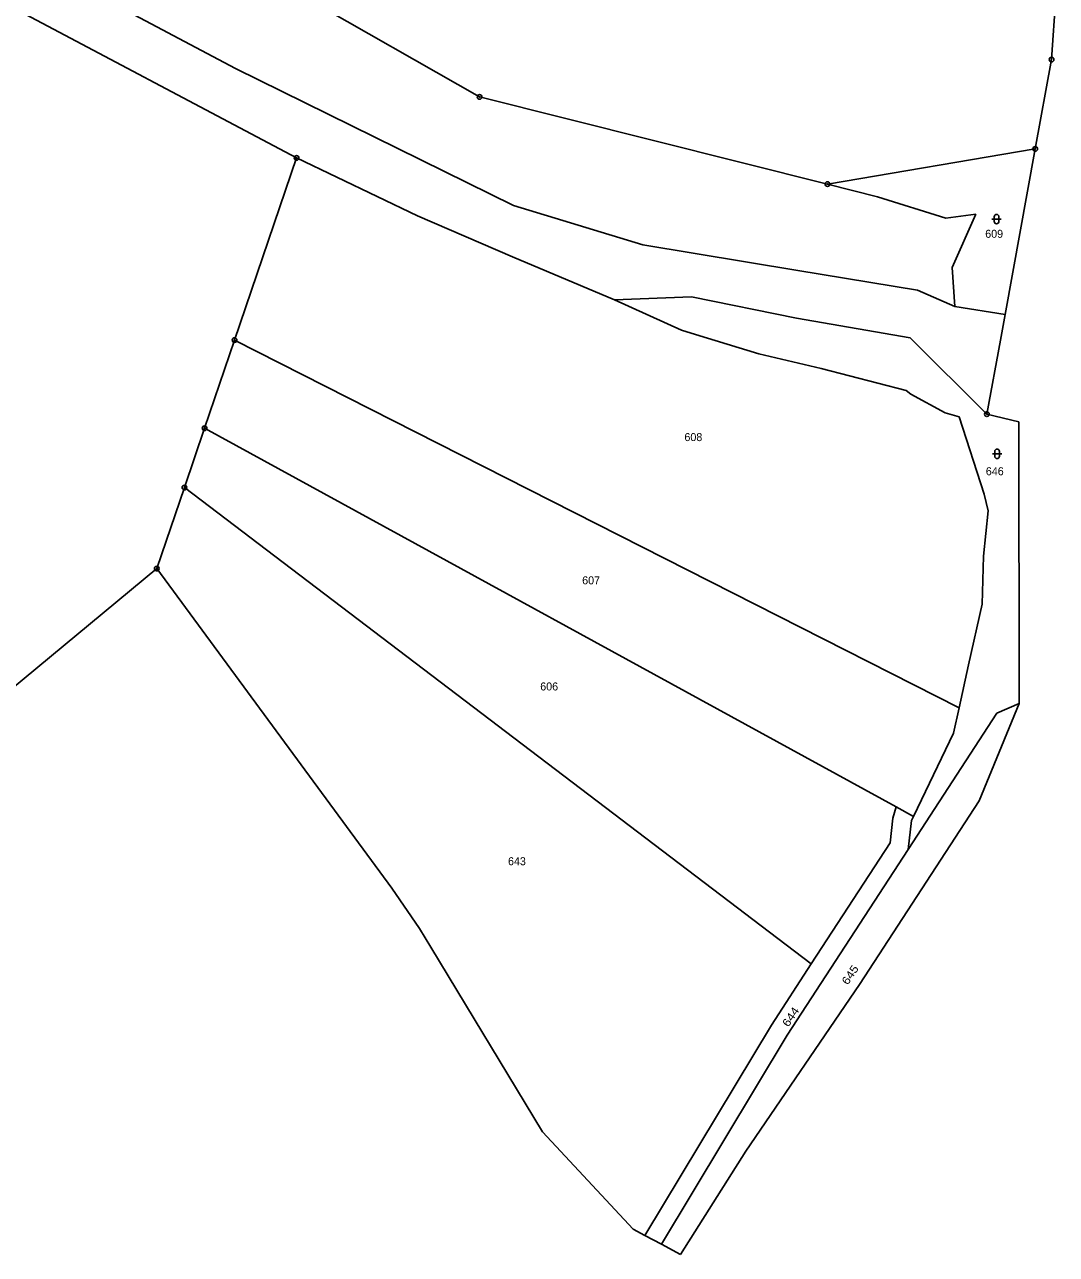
# Model space of a CAD drawing. Extents: x -719614 to -717765, y -1095834 to -1093862.
# Drawn here: x -718549.9 to -718330.6, y -1095834.3 to -1095573 of the extents above; entities that cross this region are included whole.
import ezdxf
from ezdxf.enums import TextEntityAlignment as Align

# ---------------------------------------------------------------- set-up
doc = ezdxf.new("R2010")
doc.units = 0
doc.header["$LTSCALE"] = 0.68
for name, color, linetype, lineweight in [('1', 7, 'Continuous', 25), ('3', 7, 'Continuous', 25), ('8', 7, 'Continuous', 25)]:
    doc.layers.add(name, color=color, linetype=linetype, lineweight=lineweight)
doc.layers.add('2', color=7, linetype='Continuous')

msp = doc.modelspace()

# ---------------------------------------------------------------- linework, layer by layer
at = {"layer": '1'}
for p, q in [((-718453.18, -1095588.42), (-718515.95, -1095552.63)), ((-718492.07, -1095601.38), (-718570.21, -1095559.91)), ((-718546.41, -1095560.42), (-718505.05, -1095582.36)), ((-718331.65, -1095580.47), (-718330.61, -1095565.64)), ((-718335.11, -1095599.47), (-718331.65, -1095580.47)), ((-718505.05, -1095582.36), (-718445.99, -1095611.48)), ((-718379.27, -1095606.93), (-718453.18, -1095588.42)), ((-718335.11, -1095599.47), (-718379.27, -1095606.93)), ((-718341.52, -1095634.63), (-718335.11, -1095599.47)), ((-718492.07, -1095601.38), (-718505.25, -1095640.08)), ((-718466.41, -1095613.67), (-718492.07, -1095601.38)), ((-718368.62, -1095609.67), (-718379.27, -1095606.93)), ((-718354.14, -1095614.19), (-718368.62, -1095609.67)), ((-718446.22, -1095622.37), (-718466.41, -1095613.67)), ((-718445.99, -1095611.48), (-718418.5, -1095619.84)), ((-718347.72, -1095613.35), (-718354.14, -1095614.19)), ((-718352.74, -1095624.66), (-718347.72, -1095613.35)), ((-718418.5, -1095619.84), (-718385.59, -1095625.29)), ((-718424.54, -1095631.55), (-718446.22, -1095622.37)), ((-718385.59, -1095625.29), (-718360.12, -1095629.49)), ((-718352.21, -1095632.95), (-718352.74, -1095624.66)), ((-718408.18, -1095630.92), (-718424.54, -1095631.55)), ((-718424.54, -1095631.55), (-718410.25, -1095637.96)), ((-718385.84, -1095635.43), (-718408.18, -1095630.92)), ((-718360.12, -1095629.49), (-718352.21, -1095632.95)), ((-718352.21, -1095632.95), (-718341.52, -1095634.63)), ((-718361.72, -1095639.58), (-718385.84, -1095635.43)), ((-718342.51, -1095640.06), (-718341.52, -1095634.63)), ((-718410.25, -1095637.96), (-718407.28, -1095638.86)), ((-718407.28, -1095638.86), (-718393.86, -1095642.96)), ((-718345.38, -1095655.81), (-718361.72, -1095639.58)), ((-718505.25, -1095640.08), (-718511.63, -1095658.81)), ((-718351.29, -1095718.23), (-718505.25, -1095640.08)), ((-718345.38, -1095655.81), (-718342.51, -1095640.06)), ((-718393.86, -1095642.96), (-718380.6, -1095646.13)), ((-718380.6, -1095646.13), (-718362.52, -1095650.81)), ((-718362.52, -1095650.81), (-718361.58, -1095651.56)), ((-718361.58, -1095651.56), (-718354.28, -1095655.52)), ((-718354.28, -1095655.52), (-718351.27, -1095656.35)), ((-718351.27, -1095656.35), (-718345.95, -1095672.84)), ((-718338.63, -1095657.45), (-718345.38, -1095655.81)), ((-718338.5, -1095717.31), (-718338.63, -1095657.45)), ((-718515.92, -1095671.4), (-718511.63, -1095658.81)), ((-718511.63, -1095658.81), (-718364.66, -1095739.25)), ((-718521.78, -1095688.61), (-718515.92, -1095671.4)), ((-718382.7, -1095772.61), (-718515.92, -1095671.4)), ((-718345.95, -1095672.84), (-718345.13, -1095676.36)), ((-718345.13, -1095676.36), (-718346.08, -1095686)), ((-718346.08, -1095686), (-718346.36, -1095696.19)), ((-718567.06, -1095726.1), (-718521.78, -1095688.61)), ((-718521.78, -1095688.61), (-718471.84, -1095756.54)), ((-718346.36, -1095696.19), (-718349.31, -1095709.06)), ((-718349.31, -1095709.06), (-718351.29, -1095718.23)), ((-718347.03, -1095737.95), (-718338.5, -1095717.31)), ((-718338.5, -1095717.31), (-718343.24, -1095719.32)), ((-718343.24, -1095719.32), (-718362.1, -1095748.29)), ((-718352.45, -1095723.58), (-718351.29, -1095718.23)), ((-718360.97, -1095741.27), (-718352.45, -1095723.58)), ((-718372.42, -1095776.98), (-718347.03, -1095737.95)), ((-718365.96, -1095746.87), (-718365.35, -1095741.65)), ((-718365.35, -1095741.65), (-718364.66, -1095739.25)), ((-718364.66, -1095739.25), (-718360.97, -1095741.27)), ((-718360.97, -1095741.27), (-718361.38, -1095742.12)), ((-718361.38, -1095742.12), (-718362.1, -1095748.29)), ((-718382.7, -1095772.61), (-718365.96, -1095746.87)), ((-718362.1, -1095748.29), (-718387.8, -1095787.77)), ((-718471.84, -1095756.54), (-718465.95, -1095765.08)), ((-718465.95, -1095765.08), (-718463.56, -1095769.04)), ((-718463.56, -1095769.04), (-718439.84, -1095808.28)), ((-718391.19, -1095785.65), (-718382.7, -1095772.61)), ((-718396.63, -1095812.37), (-718372.42, -1095776.98)), ((-718418.05, -1095830.27), (-718391.19, -1095785.65)), ((-718387.8, -1095787.77), (-718414.52, -1095832.16)), ((-718439.84, -1095808.28), (-718420.52, -1095828.94)), ((-718410.49, -1095834.32), (-718396.63, -1095812.37)), ((-718420.52, -1095828.94), (-718418.05, -1095830.27)), ((-718418.05, -1095830.27), (-718414.52, -1095832.16)), ((-718414.52, -1095832.16), (-718410.49, -1095834.32))]:
    msp.add_line(p, q, dxfattribs=at)
at = {"layer": '3'}
for p, q in [((-718344.341, -1095614.361), (-718342.339, -1095614.361)), ((-718343.841, -1095613.861), (-718343.841, -1095614.862)), ((-718342.839, -1095614.862), (-718342.839, -1095613.861)), ((-718344.221, -1095664.241), (-718342.219, -1095664.241)), ((-718343.721, -1095663.741), (-718343.721, -1095664.742)), ((-718342.719, -1095664.742), (-718342.719, -1095663.741))]:
    msp.add_line(p, q, dxfattribs=at)
for centre, start, end in [((-718343.34, -1095613.8609), 0, 180), ((-718343.34, -1095614.8609), 180, 359.98789), ((-718343.22, -1095663.7409), 0, 180), ((-718343.22, -1095664.7409), 180, 359.98789)]:
    msp.add_arc(centre, 0.5, start, end, dxfattribs=at)
at = {"layer": '8'}
for centre, radius in [((-718331.65, -1095580.4699), 0.5), ((-718331.65, -1095580.4699), 0.0303), ((-718453.18, -1095588.4199), 0.5), ((-718453.18, -1095588.4199), 0.0303), ((-718335.11, -1095599.4699), 0.5), ((-718335.11, -1095599.4699), 0.0303), ((-718492.07, -1095601.3799), 0.5), ((-718492.07, -1095601.3799), 0.0303), ((-718379.27, -1095606.9299), 0.5), ((-718379.27, -1095606.9299), 0.0303), ((-718505.25, -1095640.0799), 0.5), ((-718505.25, -1095640.0799), 0.0303), ((-718345.38, -1095655.8099), 0.5), ((-718345.38, -1095655.8099), 0.0303), ((-718511.63, -1095658.8099), 0.5), ((-718511.63, -1095658.8099), 0.0303), ((-718515.92, -1095671.3999), 0.5), ((-718515.92, -1095671.3999), 0.0303), ((-718521.78, -1095688.6099), 0.5), ((-718521.78, -1095688.6099), 0.0303)]:
    msp.add_circle(centre, radius, dxfattribs=at)

# ---------------------------------------------------------------- texts
at = {"layer": '2'}
for s, p in [('609', (-718343.839, -1095618.342)), ('608', (-718407.759, -1095661.532)), ('646', (-718343.709, -1095668.792)), ('607', (-718429.489, -1095691.962)), ('606', (-718438.399, -1095714.512)), ('643', (-718445.249, -1095751.642))]:
    msp.add_text(s, height=1.7, dxfattribs=at).set_placement(p, align=Align.CENTER)
at = {"layer": '2', "width": 1.15}
for s, p in [('645', (-718373.7424, -1095775.3943)), ('644', (-718386.3724, -1095784.3243))]:
    msp.add_text(s, height=1.7, rotation=56, dxfattribs=at).set_placement(p, align=Align.CENTER)

doc.saveas('drawing.dxf')
